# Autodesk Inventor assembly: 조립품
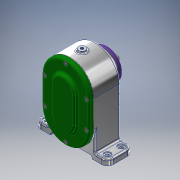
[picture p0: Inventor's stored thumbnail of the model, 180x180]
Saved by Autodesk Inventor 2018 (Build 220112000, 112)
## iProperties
Created: 2021-05
Part Number: 조립품
Material: 일반
Document SubType Name: Assembly
Designer: Admin
Author: Admin
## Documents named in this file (19)
- C:\Users\Admin\Desktop\710509V1006\710509V1006\조립품.iam
- C:\Users\Admin\Desktop\710509V1006\본체.ipt
- C:\Users\Admin\Desktop\710509V1006\710509V1006\베어링 6001.ipt
- 베어링 6001.ipt
- C:\Users\Admin\Desktop\710509V1006\710509V1006\축 A.ipt
- C:\Users\Admin\Desktop\710509V1006\710509V1006\축 B.ipt
- C:\Users\Admin\Desktop\710509V1006\710509V1006\스퍼기어 A.ipt
- C:\Users\Admin\Desktop\710509V1006\710509V1006\스퍼기어 B.ipt
- C:\Users\Admin\Desktop\710509V1006\710509V1006\커버 A.ipt
- C:\Users\Admin\Desktop\710509V1006\710509V1006\베어링 6002.ipt
- 베어링 6002.ipt
- C:\Users\Admin\Desktop\710509V1006\710509V1006\칼라.ipt
- C:\Users\Admin\Desktop\710509V1006\710509V1006\키 4 x 4 x 12.ipt
- C:\Users\Admin\Desktop\710509V1006\710509V1006\키 5 x 5 x 12.ipt
- C:\Users\Admin\Desktop\710509V1006\710509V1006\커버 B.ipt
- C:\Users\Admin\Desktop\710509V1006\710509V1006\오일 실 12 22 7.ipt
- C:\Users\Admin\Desktop\710509V1006\710509V1006\개스킷 A.ipt
- C:\Users\Admin\Desktop\710509V1006\710509V1006\개스킷 B.ipt
- C:\Users\Admin\Desktop\710509V1006\710509V1006\볼트 M4.ipt
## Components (2 placed, 2 different names)
1. 개스킷 A:1
2. 개스킷 B:1
